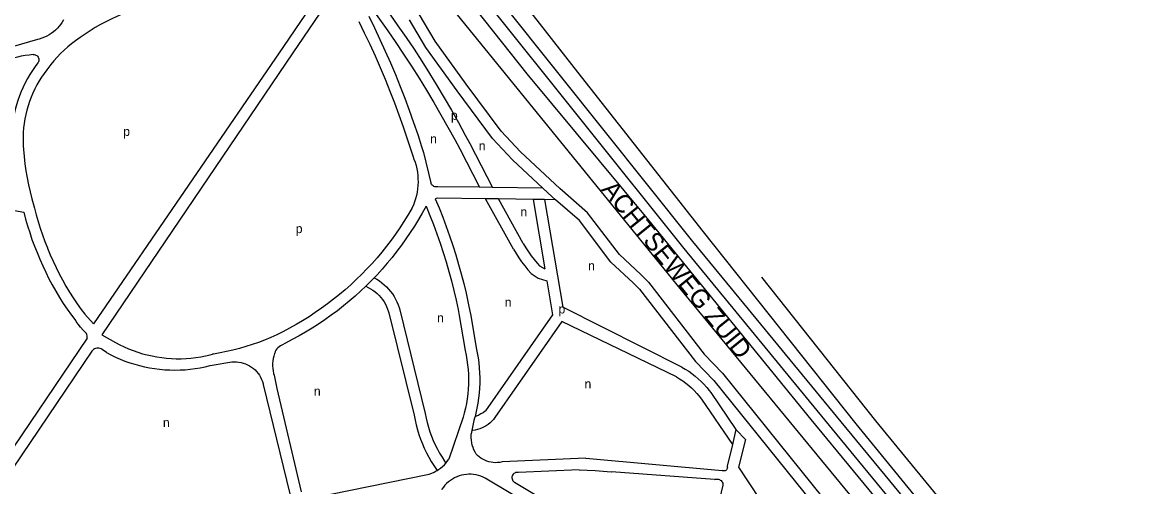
# Model space of a CAD drawing. Extents: x 157155 to 159285, y 385001 to 386651.
# Drawn here: x 158780.5 to 159272.2, y 385399.2 to 385603.8 of the extents above; entities that cross this region are included whole.
import ezdxf

# ---------------------------------------------------------------- set-up
doc = ezdxf.new("R2010")
doc.units = 0
for name, color, linetype in [('BLT_Basislijn', 7, 'Continuous'), ('BLT_Centroide', 7, 'Continuous'), ('BLT_Spoorlijn', 7, 'Continuous'), ('BLT_Straatnaam_hoofdweg', 7, 'Continuous')]:
    doc.layers.add(name, color=color, linetype=linetype)

msp = doc.modelspace()

# ---------------------------------------------------------------- linework, layer by layer
at = {"layer": 'BLT_Basislijn'}
for p, q in [((158912.81, 385618.44), (158895.56, 385593.1)), ((158916.94, 385615.62), (158899.7, 385590.29)), ((158976.88, 385614), (159002.97, 385581.07)), ((159070.44, 385486.48), (158972.27, 385607.08)), ((158787.14, 385596.2), (158776.65, 385593.14)), ((158895.56, 385593.1), (158811.92, 385470.92)), ((158899.7, 385590.29), (158815.49, 385466.04)), ((159002.97, 385581.07), (159056.49, 385516.62)), ((158973.33, 385548.02), (158982.02, 385531.07)), ((158977.75, 385550.36), (158987.77, 385530.99)), ((158957.35, 385546.35), (158960.59, 385533.03)), ((158982.02, 385531.07), (158963.69, 385531.33)), ((158987.77, 385530.99), (158982.02, 385531.07)), ((159010.02, 385530.67), (158987.77, 385530.99)), ((158984.61, 385526.03), (158963.62, 385526.33)), ((158990.38, 385525.95), (158984.61, 385526.03)), ((158996.99, 385503.8), (158984.61, 385526.03)), ((159001.32, 385506.3), (158990.38, 385525.95)), ((159005.65, 385525.74), (158990.38, 385525.95)), ((159010.74, 385525.66), (159005.65, 385525.74)), ((159005.65, 385525.74), (159010.8, 385495.24)), ((159015.58, 385525.59), (159010.74, 385525.66)), ((159010.74, 385525.66), (159018.72, 385478.32)), ((159056.49, 385516.62), (159128.06, 385428.8)), ((159008.47, 385496.47), (159010.8, 385495.24)), ((159053.2, 385492.65), (159056.57, 385489.25)), ((159052.62, 385486.19), (159049.78, 385489)), ((159071.24, 385451.89), (159018.72, 385478.32)), ((158808.08, 385475.15), (158811.92, 385470.92)), ((158942.06, 385475.79), (158953.19, 385430.64)), ((158946.88, 385477.11), (158958.12, 385431.5)), ((158973.09, 385474.58), (158975.67, 385459.25)), ((158978, 385475.52), (158980.54, 385460.39)), ((159018.33, 385472), (158988.78, 385429.64)), ((159068.82, 385447.52), (159018.33, 385472)), ((158809.08, 385464.65), (158741.28, 385364.66)), ((158815.49, 385466.04), (158821.51, 385462.68)), ((158811.18, 385458.84), (158772.26, 385401.45)), ((158817.57, 385458.29), (158815.61, 385459.59)), ((158864.12, 385452.72), (158872.88, 385454.16)), ((158891.5, 385448.32), (158892.69, 385442.52)), ((158886.71, 385444.19), (158898.45, 385396.07)), ((158892.69, 385442.52), (158903.39, 385396.93)), ((159083.98, 385440.7), (159095.1, 385424.37)), ((159079.94, 385437.74), (159093.52, 385417.81)), ((158974.78, 385429.76), (158968.47, 385411.33)), ((158984.75, 385432.61), (158984.55, 385432.4)), ((158978.7, 385423.95), (158978.42, 385422.52)), ((158979.57, 385428.33), (158978.7, 385423.95)), ((159095.1, 385424.37), (159093.52, 385417.81)), ((159099.26, 385419.98), (159095.1, 385424.37)), ((159093.52, 385417.81), (159091.2, 385408.22)), ((159028.88, 385411.78), (158991.96, 385410.09)), ((159028.88, 385411.78), (159089.02, 385406.35)), ((158907.07, 385394.01), (158959.9, 385404.76)), ((159025.91, 385406.65), (158999.23, 385405.44)), ((159085.61, 385402.31), (159040.28, 385405.73)), ((159045.49, 385366.59), (158984.59, 385402.96)), ((159048.05, 385370.89), (158997.45, 385401.11)), ((159089.33, 385399.83), (159085.29, 385382.94))]:
    msp.add_line(p, q, dxfattribs=at)
for points in [[(158939.39, 385669.9), (159072.13, 385504.06), (159137.44, 385424.52)], [(158927.27, 385627.52), (158931.16, 385622.57), (158934.99, 385617.57), (158938.76, 385612.52), (158942.46, 385607.42), (158946.09, 385602.28), (158949.66, 385597.09), (158953.16, 385591.86), (158956.6, 385586.58), (158959.97, 385581.26), (158963.27, 385575.9), (158966.5, 385570.5), (158969.66, 385565.05), (158972.76, 385559.57), (158975.78, 385554.05), (158977.75, 385550.36)], [(158837.23, 385611.37), (158834.65, 385610.72), (158832.09, 385609.99), (158829.55, 385609.18), (158827.04, 385608.29), (158824.55, 385607.33), (158822.1, 385606.3), (158819.67, 385605.19), (158817.29, 385604.02), (158814.93, 385602.77), (158812.62, 385601.45), (158810.35, 385600.06), (158808.12, 385598.6), (158805.94, 385597.08), (158803.92, 385595.58)], [(158930.48, 385615.24), (158934.24, 385610.22), (158937.93, 385605.16), (158941.55, 385600.05), (158945.11, 385594.89), (158948.6, 385589.69), (158952.03, 385584.45), (158955.39, 385579.16), (158958.68, 385573.83), (158961.9, 385568.46), (158965.06, 385563.04), (158968.14, 385557.59), (158971.15, 385552.1), (158973.33, 385548.02)], [(158933.27, 385606.42), (158935.75, 385601.35), (158938.16, 385596.26), (158940.5, 385591.12), (158942.76, 385585.96), (158944.95, 385580.76), (158947.07, 385575.54), (158949.11, 385570.28), (158951.07, 385565), (158952.97, 385559.69), (158954.78, 385554.35), (158956.52, 385548.99), (158957.35, 385546.35)], [(159053.2, 385492.65), (159043.72, 385501.52), (159029.71, 385519.9), (159017.44, 385530.61), (159000.13, 385546.68), (158991.59, 385555.84), (158976.15, 385576.54), (158962.56, 385595.39), (158955.47, 385607.42)], [(158798.64, 385604.91), (158798.06, 385603.89), (158797.41, 385602.92), (158796.69, 385602), (158795.92, 385601.12), (158795.08, 385600.31), (158794.2, 385599.55), (158793.26, 385598.85), (158792.27, 385598.22), (158791.25, 385597.66), (158790.19, 385597.17), (158789.1, 385596.75), (158787.98, 385596.41), (158787.14, 385596.2)], [(158928.8, 385604.18), (158931.26, 385599.15), (158933.65, 385594.09), (158935.98, 385588.99), (158938.22, 385583.86), (158940.4, 385578.69), (158942.5, 385573.5), (158944.52, 385568.27), (158946.47, 385563.02), (158948.35, 385557.74), (158950.15, 385552.44), (158951.87, 385547.11), (158952.57, 385544.88)], [(159010.02, 385530.67), (158996.6, 385543.14), (158987.75, 385552.63), (158972.12, 385573.59), (158958.37, 385592.66), (158951.17, 385604.88)], [(158803.92, 385595.58), (158802.2, 385594.27), (158800.54, 385592.89), (158798.92, 385591.45), (158797.36, 385589.95), (158795.86, 385588.4), (158794.41, 385586.79), (158793.03, 385585.13), (158791.71, 385583.42), (158791.29, 385582.86)], [(158785.26, 385589.51), (158783.5, 385589.35), (158781.76, 385589.12), (158780.03, 385588.8), (158778.31, 385588.4), (158776.62, 385587.93), (158774.95, 385587.38), (158773.3, 385586.76), (158771.68, 385586.06), (158770.1, 385585.29), (158768.56, 385584.44), (158767.05, 385583.53), (158765.59, 385582.55), (158764.17, 385581.51), (158762.81, 385580.4), (158762.2, 385579.88)], [(158785.26, 385589.51), (158785.68, 385589.52), (158786.1, 385589.45), (158786.5, 385589.3), (158786.86, 385589.08), (158787.18, 385588.8), (158787.44, 385588.46), (158787.63, 385588.08), (158787.74, 385587.67), (158787.78, 385587.25), (158787.74, 385586.82), (158787.62, 385586.42), (158787.42, 385586.04), (158787.35, 385585.93)], [(158787.35, 385585.93), (158786.09, 385584.25), (158784.9, 385582.53), (158783.78, 385580.76), (158782.73, 385578.96), (158781.74, 385577.11), (158780.83, 385575.23), (158779.99, 385573.31), (158779.22, 385571.36), (158778.53, 385569.39), (158777.91, 385567.38), (158777.37, 385565.36), (158776.91, 385563.32), (158776.53, 385561.26), (158776.23, 385559.19), (158776, 385557.11), (158775.86, 385555.02), (158775.79, 385552.93), (158775.81, 385550.84), (158775.9, 385548.75), (158776.02, 385547.18)], [(158791.29, 385582.86), (158790.1, 385581.26), (158788.97, 385579.61), (158787.91, 385577.92), (158786.91, 385576.19), (158785.99, 385574.43), (158785.14, 385572.62), (158784.36, 385570.78), (158783.65, 385568.92), (158783.02, 385567.02), (158782.47, 385565.11), (158781.99, 385563.17), (158781.6, 385561.21), (158781.28, 385559.24), (158781.04, 385557.26), (158780.88, 385555.27), (158780.8, 385553.28), (158780.8, 385551.29), (158780.88, 385549.29), (158781, 385547.72)], [(158781, 385547.72), (158781.29, 385544.58), (158781.65, 385541.46), (158782.1, 385538.34), (158782.63, 385535.24), (158783.24, 385532.15), (158783.92, 385529.07), (158784.68, 385526.02), (158785.52, 385522.98), (158785.85, 385521.88)], [(158952.57, 385544.88), (158953.13, 385543.51), (158953.63, 385542.11), (158954.04, 385540.69), (158954.38, 385539.25), (158954.64, 385537.79), (158954.82, 385536.32), (158954.92, 385534.84), (158954.94, 385533.36), (158954.88, 385531.88), (158954.74, 385530.4), (158954.53, 385528.94), (158954.23, 385527.49), (158953.86, 385526.05), (158953.4, 385524.64), (158952.88, 385523.26), (158952.27, 385521.91), (158952.17, 385521.68)], [(158963.69, 385531.33), (158963.25, 385531.25), (158962.8, 385531.25), (158962.35, 385531.33), (158961.93, 385531.49), (158961.54, 385531.72), (158961.2, 385532.01), (158960.91, 385532.36), (158960.69, 385532.76), (158960.59, 385533.03)], [(159015.58, 385525.59), (159014.09, 385526.89), (159010.02, 385530.67)], [(158769.51, 385525.69), (158772.85, 385521.6), (158781.13, 385520.12)], [(158958.45, 385522.71), (158956.82, 385519.75), (158955.12, 385516.83), (158953.36, 385513.95), (158951.52, 385511.11), (158949.62, 385508.32), (158947.65, 385505.58), (158945.62, 385502.88), (158943.53, 385500.23), (158941.37, 385497.63), (158939.15, 385495.08), (158936.88, 385492.59), (158935.61, 385491.26)], [(158958.45, 385522.71), (158960.11, 385518.7), (158961.7, 385514.66), (158963.21, 385510.59), (158964.65, 385506.49), (158966.01, 385502.37), (158967.3, 385498.23), (158968.51, 385494.06), (158969.64, 385489.87), (158970.7, 385485.66), (158971.68, 385481.43), (158972.58, 385477.18), (158973.09, 385474.58)], [(158963.62, 385526.33), (158963, 385526.19), (158962.47, 385526.01)], [(158962.47, 385526.01), (158964.18, 385521.97), (158965.81, 385517.89), (158967.37, 385513.79), (158968.85, 385509.66), (158970.25, 385505.51), (158971.58, 385501.33), (158972.84, 385497.12), (158974.01, 385492.9), (158975.11, 385488.65), (158976.13, 385484.39), (158977.08, 385480.1), (158977.94, 385475.8), (158978, 385475.52)], [(159049.78, 385489), (159040, 385498.16), (159026.05, 385516.46), (159015.58, 385525.59)], [(158781.13, 385520.12), (158781.92, 385517.1), (158782.78, 385514.09), (158783.73, 385511.11), (158784.74, 385508.15), (158785.84, 385505.22), (158787.01, 385502.3)], [(158785.85, 385521.88), (158786.61, 385518.91), (158787.44, 385515.96), (158788.35, 385513.04), (158789.34, 385510.14), (158790.41, 385507.27), (158791.54, 385504.42), (158791.63, 385504.23)], [(158952.17, 385521.68), (158950.48, 385518.82), (158948.74, 385516), (158946.92, 385513.22), (158945.03, 385510.49), (158943.09, 385507.81), (158941.07, 385505.17), (158939, 385502.58), (158936.86, 385500.04), (158934.66, 385497.56), (158932.4, 385495.13), (158930.09, 385492.75), (158927.71, 385490.43), (158925.29, 385488.17), (158922.81, 385485.97), (158920.27, 385483.83), (158917.69, 385481.74), (158915.06, 385479.73), (158912.37, 385477.77), (158909.65, 385475.89), (158906.87, 385474.06), (158904.06, 385472.31), (158901.2, 385470.62), (158898.3, 385469.01), (158895.37, 385467.46), (158892.66, 385466.11)], [(158791.63, 385504.23), (158792.79, 385501.37), (158794.03, 385498.54), (158795.34, 385495.75), (158796.72, 385492.99), (158798.18, 385490.27), (158799.7, 385487.59), (158801.29, 385484.95), (158802.95, 385482.35), (158804.68, 385479.79), (158806.48, 385477.28), (158808.08, 385475.15)], [(158996.99, 385503.8), (158998.13, 385501.89), (158999.35, 385500.03), (159000.62, 385498.2), (159001.97, 385496.43), (159003.37, 385494.7), (159004.76, 385493.11)], [(159001.32, 385506.3), (159002.42, 385504.47), (159003.59, 385502.68), (159004.82, 385500.93), (159006.12, 385499.24), (159007.48, 385497.59), (159008.47, 385496.47)], [(158787.01, 385502.3), (158788.2, 385499.38), (158789.47, 385496.5), (158790.8, 385493.65), (158792.21, 385490.83), (158793.69, 385488.05), (158795.24, 385485.31), (158796.86, 385482.61), (158798.55, 385479.95), (158800.3, 385477.34), (158802.12, 385474.77), (158804.01, 385472.24), (158804.18, 385472.02)], [(159004.76, 385493.11), (159007.86, 385491.06), (159011.71, 385489.85)], [(158935.61, 385491.26), (158934.54, 385490.15), (158932.15, 385487.76), (158931.89, 385487.51)], [(158935.61, 385491.26), (158936.79, 385490.58), (158937.93, 385489.84), (158939.01, 385489.03), (158940.05, 385488.16), (158941.03, 385487.23), (158941.95, 385486.25), (158942.82, 385485.21), (158943.62, 385484.12), (158944.36, 385482.98), (158945.02, 385481.81), (158945.62, 385480.6), (158946.15, 385479.35), (158946.6, 385478.07), (158946.88, 385477.11)], [(159011.71, 385489.85), (159014.23, 385474.87), (158984.75, 385432.61)], [(159056.57, 385489.25), (159081.04, 385457.65), (159089.1, 385449.28), (159133.4, 385394.34), (159144.82, 385374.87), (159147.86, 385371.84)], [(158931.89, 385487.51), (158929.7, 385485.43), (158927.2, 385483.17), (158924.64, 385480.96), (158922.04, 385478.81), (158919.38, 385476.73), (158916.67, 385474.71), (158913.92, 385472.75), (158911.12, 385470.86), (158908.28, 385469.04), (158905.39, 385467.28), (158902.46, 385465.59), (158899.5, 385463.98), (158896.5, 385462.43), (158894.84, 385461.61)], [(158931.89, 385487.51), (158932.97, 385487), (158934.02, 385486.42), (158935.02, 385485.77), (158935.98, 385485.05), (158936.89, 385484.28), (158937.74, 385483.44), (158938.54, 385482.55), (158939.27, 385481.61), (158939.94, 385480.61), (158940.55, 385479.58), (158941.08, 385478.51), (158941.54, 385477.41), (158941.92, 385476.28), (158942.06, 385475.79)], [(159052.62, 385486.19), (159077.25, 385454.38), (159085.34, 385445.97), (159129.27, 385391.49), (159140.84, 385371.79), (159145.33, 385367.3)], [(159153.62, 385385.45), (159149.35, 385390.74), (159070.44, 385486.48)], [(158808.54, 385466.97), (158807.34, 385468.19), (158806.19, 385469.46), (158805.1, 385470.79), (158804.18, 385472.02)], [(158809.08, 385464.65), (158809.11, 385465.16), (158809.06, 385465.67), (158808.93, 385466.17), (158808.73, 385466.65), (158808.54, 385466.97)], [(158892.66, 385466.11), (158889.99, 385464.92), (158887.29, 385463.81), (158884.55, 385462.77), (158881.79, 385461.8), (158879.01, 385460.91), (158876.2, 385460.09), (158873.36, 385459.36), (158870.51, 385458.7), (158867.65, 385458.12), (158864.76, 385457.61), (158864.39, 385457.55)], [(158815.61, 385459.59), (158815.2, 385459.86), (158814.74, 385460.06), (158814.27, 385460.18), (158813.77, 385460.23), (158813.28, 385460.19), (158812.8, 385460.08), (158812.34, 385459.89), (158811.92, 385459.63), (158811.55, 385459.3), (158811.18, 385458.84)], [(158817.57, 385458.29), (158819.56, 385457.25), (158821.59, 385456.28), (158823.65, 385455.38), (158825.74, 385454.56), (158827.86, 385453.81), (158830.01, 385453.14), (158832.18, 385452.54), (158834.36, 385452.03), (158836.57, 385451.59), (158838.79, 385451.23), (158841.02, 385450.95), (158843.26, 385450.74), (158845.5, 385450.62), (158847.75, 385450.58), (158850, 385450.62), (158852.24, 385450.74), (158854.48, 385450.93), (158856.71, 385451.21), (158858.93, 385451.57), (158861.14, 385452), (158863.33, 385452.52), (158864.12, 385452.72)], [(158821.51, 385462.68), (158823.43, 385461.68), (158825.38, 385460.75), (158827.36, 385459.9), (158829.37, 385459.12), (158831.41, 385458.42), (158833.47, 385457.79), (158835.56, 385457.24), (158837.66, 385456.77), (158839.78, 385456.37), (158841.92, 385456.06), (158844.06, 385455.82), (158846.21, 385455.67), (158848.37, 385455.59), (158850.53, 385455.59), (158852.68, 385455.67), (158854.83, 385455.84), (158856.98, 385456.08), (158859.11, 385456.4), (158861.23, 385456.8), (158863.33, 385457.28), (158864.39, 385457.55)], [(158894.84, 385461.61), (158894.24, 385461.28), (158893.67, 385460.88), (158893.16, 385460.42), (158892.7, 385459.9), (158892.31, 385459.33), (158891.99, 385458.72), (158891.74, 385458.08), (158891.65, 385457.8)], [(158975.67, 385459.25), (158976.12, 385457.15), (158976.49, 385455.04), (158976.78, 385452.91), (158976.99, 385450.78), (158977.12, 385448.64), (158977.17, 385446.49), (158977.14, 385444.35), (158977.03, 385442.2), (158976.85, 385440.07), (158976.58, 385437.94), (158976.23, 385435.82), (158975.8, 385433.72), (158975.3, 385431.63), (158974.78, 385429.76)], [(158980.54, 385460.39), (158981.01, 385458.2), (158981.4, 385456), (158981.71, 385453.78), (158981.94, 385451.56), (158982.09, 385449.32), (158982.17, 385447.09), (158982.16, 385444.85), (158982.07, 385442.62), (158981.9, 385440.39), (158981.65, 385438.16), (158981.33, 385435.95), (158980.92, 385433.75), (158980.44, 385431.56), (158980.07, 385430.13)], [(158872.88, 385454.16), (158873.89, 385454.22), (158874.9, 385454.21), (158875.91, 385454.11), (158876.91, 385453.93), (158877.89, 385453.67), (158878.85, 385453.34), (158879.78, 385452.93), (158880.67, 385452.46), (158881.53, 385451.91), (158882.34, 385451.3), (158883.09, 385450.62), (158883.79, 385449.89), (158884.43, 385449.1), (158885.01, 385448.27), (158885.52, 385447.39), (158885.96, 385446.48), (158886.33, 385445.54), (158886.62, 385444.56), (158886.71, 385444.19)], [(158891.65, 385457.8), (158891.33, 385456.75), (158891.08, 385455.67), (158890.92, 385454.59), (158890.83, 385453.49), (158890.82, 385452.39), (158890.89, 385451.29), (158891.04, 385450.2), (158891.27, 385449.12), (158891.5, 385448.32)], [(159071.24, 385451.89), (159072.77, 385451), (159074.27, 385450.04), (159075.71, 385449.01), (159077.12, 385447.92), (159078.46, 385446.77), (159079.76, 385445.56), (159081, 385444.29), (159082.19, 385442.96), (159083.31, 385441.59), (159083.98, 385440.7)], [(159068.82, 385447.52), (159070.26, 385446.68), (159071.65, 385445.77), (159072.99, 385444.8), (159074.29, 385443.77), (159075.54, 385442.68), (159076.73, 385441.52), (159077.86, 385440.31), (159078.94, 385439.05), (159079.94, 385437.74)], [(158953.19, 385430.64), (158953.61, 385428.5), (158954.1, 385426.38), (158954.67, 385424.28), (158955.32, 385422.2), (158956.04, 385420.15), (158956.84, 385418.12), (158957.71, 385416.13), (158958.65, 385414.17), (158959.67, 385412.24), (158960.75, 385410.36), (158961.91, 385408.51), (158963.13, 385406.71), (158963.38, 385406.36)], [(158958.12, 385431.5), (158958.52, 385429.45), (158958.99, 385427.43), (158959.55, 385425.42), (158960.18, 385423.43), (158960.88, 385421.47), (158961.66, 385419.54), (158962.52, 385417.65), (158963.45, 385415.78), (158964.44, 385413.95), (158965.51, 385412.16), (158966.65, 385410.42), (158967.2, 385409.62)], [(158988.78, 385429.64), (158988.14, 385428.81), (158987.43, 385428.03), (158986.68, 385427.31), (158985.86, 385426.65), (158985, 385426.06), (158984.1, 385425.53), (158983.16, 385425.07), (158982.19, 385424.69), (158981.19, 385424.38), (158980.17, 385424.15), (158979.13, 385423.99), (158978.7, 385423.95)], [(158980.07, 385430.13), (158979.88, 385429.4), (158979.57, 385428.33)], [(158984.55, 385432.4), (158983.64, 385431.78), (158982.68, 385431.22), (158981.68, 385430.74), (158980.66, 385430.33), (158980.07, 385430.13)], [(159128.06, 385428.8), (159165.4, 385383.51), (159195.02, 385345.77)], [(159137.44, 385424.52), (159206.62, 385340.75), (159272.21, 385260.25)], [(158980.59, 385413.5), (158980.05, 385414.45), (158979.58, 385415.44), (158979.19, 385416.46), (158978.87, 385417.5), (158978.63, 385418.57), (158978.46, 385419.65), (158978.38, 385420.74), (158978.38, 385421.83), (158978.42, 385422.52)], [(159099.26, 385419.98), (159096.23, 385407.84), (159134.13, 385350.33)], [(158963.38, 385406.36), (158963.95, 385406.72), (158964.87, 385407.38), (158965.73, 385408.1), (158966.54, 385408.89), (158967.2, 385409.62)], [(158967.2, 385409.62), (158967.3, 385409.73), (158967.99, 385410.62), (158968.47, 385411.33)], [(158991.96, 385410.09), (158991.01, 385409.91), (158990.04, 385409.8), (158989.06, 385409.78), (158988.09, 385409.83), (158987.12, 385409.97), (158986.17, 385410.18), (158985.24, 385410.47), (158984.33, 385410.83), (158983.46, 385411.27), (158982.63, 385411.78), (158981.84, 385412.36), (158981.1, 385412.99), (158980.59, 385413.5)], [(158959.9, 385404.76), (158960.96, 385405.14), (158961.99, 385405.6), (158962.99, 385406.12), (158963.38, 385406.36)], [(158984.59, 385402.96), (158983.62, 385403.44), (158982.61, 385403.84), (158981.58, 385404.16), (158980.53, 385404.41), (158979.46, 385404.58), (158978.39, 385404.67), (158977.3, 385404.68), (158976.23, 385404.62), (158975.15, 385404.47), (158974.1, 385404.24), (158973.06, 385403.94), (158972.05, 385403.55), (158971.07, 385403.1), (158970.12, 385402.58), (158969.22, 385401.98), (158968.36, 385401.32), (158967.55, 385400.6), (158966.8, 385399.82), (158966.11, 385398.99), (158965.49, 385398.11), (158965.29, 385397.8)], [(158999.23, 385405.44), (158998.8, 385405.5), (158998.37, 385405.48), (158997.94, 385405.38), (158997.54, 385405.21), (158997.18, 385404.96), (158996.87, 385404.66), (158996.62, 385404.3), (158996.45, 385403.9), (158996.34, 385403.48), (158996.32, 385403.04), (158996.38, 385402.61), (158996.51, 385402.2), (158996.72, 385401.81), (158996.99, 385401.47), (158997.32, 385401.19), (158997.45, 385401.11)], [(159025.91, 385406.65), (159029.47, 385406.55), (159033.04, 385406.36), (159036.59, 385406.09), (159040.15, 385405.75), (159040.28, 385405.73)], [(159091.2, 385408.22), (159091.29, 385407.88), (159091.31, 385407.54), (159091.24, 385407.2), (159091.1, 385406.88), (159090.89, 385406.6), (159090.62, 385406.38), (159090.31, 385406.23), (159089.98, 385406.15), (159089.63, 385406.15), (159089.29, 385406.23), (159089.02, 385406.35)], [(159085.61, 385402.31), (159086.03, 385402.48), (159086.47, 385402.57), (159086.93, 385402.58), (159087.38, 385402.51), (159087.81, 385402.36), (159088.2, 385402.14), (159088.56, 385401.86), (159088.85, 385401.51), (159089.08, 385401.12), (159089.24, 385400.7), (159089.33, 385400.25), (159089.33, 385399.83)]]:
    msp.add_lwpolyline(points, dxfattribs=at)
at = {"layer": 'BLT_Spoorlijn'}
for points in [[(158990.67, 385614), (159016.99, 385580.91)], [(159000.46, 385613.69), (159025.3, 385581.86)], [(159025.3, 385581.86), (159080.59, 385511.47)], [(159016.99, 385580.91), (159075.99, 385507.23)], [(159080.59, 385511.47), (159147.93, 385426.96)], [(159075.99, 385507.23), (159141.3, 385427.7)], [(159106.37, 385491.48), (159156.57, 385428.25)], [(159141.3, 385427.7), (159210.48, 385343.93)], [(159147.93, 385426.96), (159216.74, 385342.82)], [(159156.57, 385428.25), (159228.69, 385340.61)]]:
    msp.add_lwpolyline(points, dxfattribs=at)

# ---------------------------------------------------------------- texts
at = {"layer": 'BLT_Centroide'}
for s, p in [('p', (158969.46, 385560.81)), ('p', (158824.96, 385553.7)), ('n', (158960.27, 385550.41)), ('n', (158981.69, 385547.35)), ('n', (159000.05, 385518.27)), ('p', (158901.03, 385510.89)), ('n', (159029.88, 385494.55)), ('n', (158993.16, 385478.48)), ('p', (159016.87, 385475.52)), ('n', (158963.33, 385471.59)), ('n', (159028.35, 385442.51)), ('n', (158909.03, 385439.3)), ('n', (158842.48, 385425.53))]:
    msp.add_text(s, height=4, dxfattribs=at).set_placement(p)
at = {"layer": 'BLT_Straatnaam_hoofdweg'}
msp.add_text('ACHTSEWEG ZUID', height=8, rotation=309.0181, dxfattribs=at).set_placement((159035.48, 385530.02))

doc.saveas('drawing.dxf')
